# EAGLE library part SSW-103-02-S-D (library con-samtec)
THROUGH-HOLE .025" SQ POST SOCKET Source: Samtec SSW.pdf
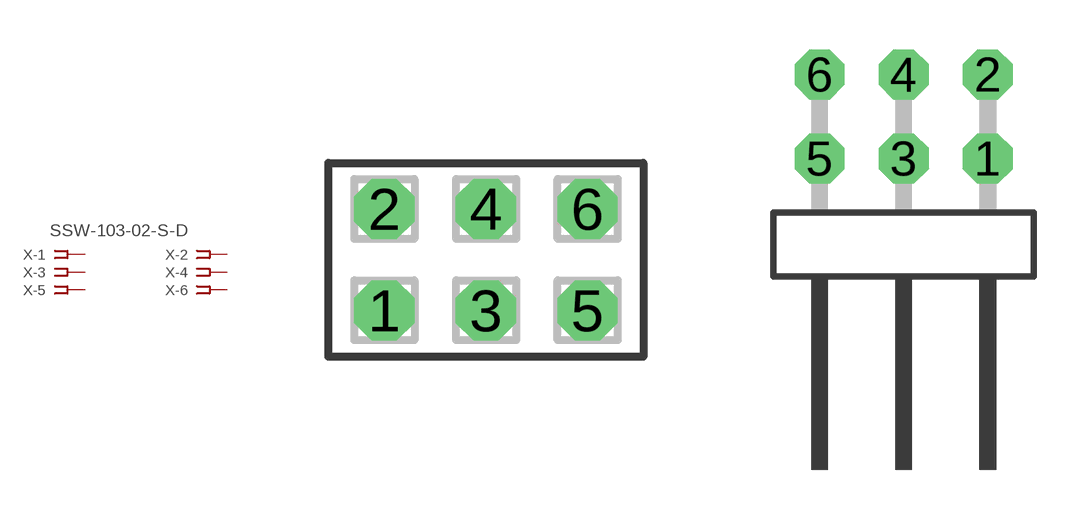
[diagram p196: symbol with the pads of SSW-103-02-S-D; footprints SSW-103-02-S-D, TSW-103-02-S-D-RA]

Designator prefix X; gates -1=FPINV -2=FPIN -3=FPIN -4=FPIN -5=FPIN -6=FPIN

## SSW-103-02-S-D (MPN: SSW-103-02-S-D; OC_FARNELL: unknown; OC_NEWARK: 11P9365)  [SSW-103-02-S-D]
1  -1:1  pas
2  -2:1  pas
3  -3:1  pas
4  -4:1  pas
5  -5:1  pas
6  -6:1  pas

## SSW-103-02-S-D-RA (MPN: SSW-103-02-S-D-RA; OC_FARNELL: unknown; OC_NEWARK: 11P9366)  [TSW-103-02-S-D-RA]
Pads as for SSW-103-02-S-D

## Footprint SSW-103-02-S-D (pad centres in mm)
THROUGH-HOLE .025" SQ POST SOCKET Source: Samtec SSW.pdf
drill 1 pad 1.5 octagon: 1 -2.54,-1.27; 2 -2.54,1.27; 3 0,-1.27; 4 0,1.27; 5 2.54,-1.27; 6 2.54,1.27

## Footprint TSW-103-02-S-D-RA (pad centres in mm)
THROUGH-HOLE .025" SQ POST HEADER Source: Samtec TSW.pdf
drill 1 pad 1.5 octagon: 1 2.54,1.524; 2 2.54,4.064; 3 0,1.524; 4 0,4.064; 5 -2.54,1.524; 6 -2.54,4.064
